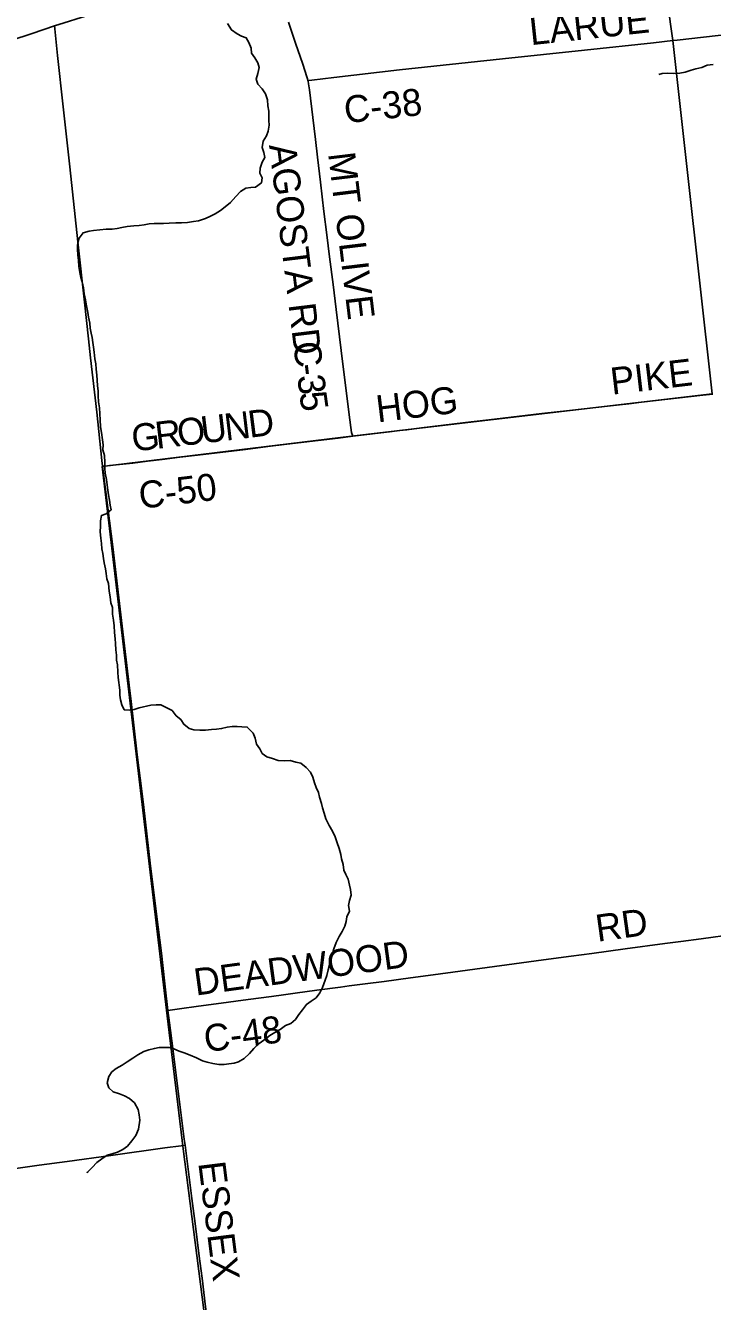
# Model space of a CAD drawing. Extents: x 1584893 to 1934202, y 663575 to 1091909.
# Drawn here: x 1740518 to 1748155, y 919866 to 934048 of the extents above; entities that cross this region are included whole.
import ezdxf

# ---------------------------------------------------------------- set-up
doc = ezdxf.new("R2010")
doc.units = 0
for name, color, linetype in [('GM_X_County_Road', 7, 'Continuous'), ('GM_X_County_Road_Text', 7, 'Continuous'), ('GM_X_Minor_River', 7, 'Continuous'), ('GM_X_Township', 7, 'Continuous')]:
    doc.layers.add(name, color=color, linetype=linetype)

msp = doc.modelspace()

# ---------------------------------------------------------------- linework, layer by layer
at = {"layer": 'GM_X_County_Road'}
for points in [[(1740840, 934043), (1740948, 934078), (1741137, 934136), (1741575, 934272), (1741827, 934348), (1741874, 934364), (1741920, 934379)], [(1747714, 933881), (1747761, 933886), (1748511, 933970), (1749147, 934042), (1749701, 934105), (1750239, 934164), (1750663, 934213), (1751430, 934296), (1751903, 934349), (1752896, 934460), (1752991, 934469), (1753049, 934473), (1753084, 934472), (1753123, 934468), (1753154, 934460), (1753192, 934449), (1753269, 934419), (1753584, 934278), (1753840, 934168), (1754320, 933956), (1754513, 933871)], [(1743657, 933436), (1743653, 933455), (1743646, 933478), (1743600, 933618), (1743521, 933851), (1743442, 934084)], [(1737758, 932862), (1737763, 932863), (1737769, 932865), (1737773, 932868), (1737788, 932878), (1737814, 932899), (1737880, 932947), (1737948, 932993), (1738004, 933027), (1738161, 933115), (1738262, 933170), (1738320, 933199), (1738380, 933225), (1738441, 933248), (1738596, 933301), (1738705, 933338), (1738814, 933373), (1739017, 933439), (1739204, 933501), (1739453, 933584), (1739842, 933713), (1740123, 933806), (1740590, 933960), (1740840, 934043)], [(1741375, 929149), (1741368, 929213), (1741310, 929752), (1741242, 930355), (1741219, 930567), (1741174, 930975), (1741099, 931644), (1741010, 932476), (1740937, 933145), (1740874, 933716), (1740844, 934010), (1740840, 934043)], [(1743657, 933436), (1743699, 933441), (1743944, 933471), (1744677, 933554), (1745819, 933678), (1746733, 933773), (1747500, 933857), (1747714, 933881)], [(1744155, 929482), (1744141, 929524), (1744115, 929720), (1744089, 929931), (1744070, 930078), (1744026, 930436), (1743970, 930892), (1743937, 931169), (1743897, 931478), (1743867, 931722), (1743836, 931982), (1743797, 932308), (1743763, 932585), (1743740, 932780), (1743711, 933025), (1743674, 933334), (1743665, 933399), (1743659, 933431), (1743657, 933436)], [(1744155, 929482), (1744594, 929537), (1744676, 929546), (1744757, 929555), (1744920, 929576), (1745409, 929635), (1745731, 929673), (1746256, 929735), (1746565, 929770), (1746826, 929799), (1747087, 929829), (1747226, 929845), (1747364, 929861), (1747788, 929909), (1748048, 929940), (1748158, 929952)], [(1741375, 929149), (1741402, 929151), (1741451, 929156), (1741712, 929184), (1741875, 929206), (1742038, 929224), (1742233, 929249), (1742429, 929272), (1742934, 929333), (1743243, 929373), (1743487, 929402), (1743992, 929462), (1744155, 929482)], [(1742101, 923100), (1742066, 923396), (1742028, 923738), (1741991, 924027), (1741905, 924738), (1741833, 925356), (1741812, 925537), (1741760, 925943), (1741687, 926568), (1741670, 926716), (1741592, 927372), (1741488, 928252), (1741434, 928686), (1741388, 929034), (1741375, 929149)], [(1742101, 923100), (1742150, 923108), (1742231, 923120), (1742442, 923149), (1742637, 923174), (1742994, 923223), (1743254, 923257), (1743384, 923275), (1743514, 923293), (1743758, 923325), (1744018, 923361), (1744115, 923374), (1744294, 923397), (1744505, 923424), (1744798, 923462), (1744993, 923489), (1745269, 923526), (1745512, 923559), (1745870, 923606), (1746113, 923640), (1746276, 923662), (1746584, 923703), (1746812, 923733), (1747186, 923784), (1747624, 923843), (1747803, 923866), (1748030, 923897), (1748404, 923947)], [(1742292, 921603), (1742283, 921670), (1742245, 921968), (1742181, 922469), (1742155, 922679), (1742118, 922964), (1742101, 923100)], [(1740410, 921342), (1740670, 921379), (1740979, 921422), (1741467, 921489), (1742068, 921572), (1742247, 921597), (1742292, 921603)], [(1742935, 916518), (1742930, 916557), (1742859, 917127), (1742812, 917485), (1742736, 918096), (1742717, 918251), (1742672, 918615), (1742623, 919006), (1742595, 919238), (1742569, 919432), (1742547, 919591), (1742519, 919807), (1742481, 920123), (1742449, 920369), (1742403, 920731), (1742368, 921009), (1742329, 921306), (1742292, 921603)]]:
    msp.add_lwpolyline(points, dxfattribs=at)
at = {"layer": 'GM_X_Minor_River'}
for points in [[(1742764, 934069), (1742807, 934000), (1742869, 933955), (1742920, 933930), (1742972, 933911), (1743001, 933860), (1743028, 933796), (1743029, 933740), (1743067, 933689), (1743100, 933632), (1743115, 933580), (1743102, 933514), (1743081, 933452), (1743100, 933398), (1743149, 933345), (1743184, 933290), (1743207, 933223), (1743212, 933157), (1743221, 933097), (1743224, 933043), (1743223, 932993), (1743225, 932940), (1743215, 932874), (1743195, 932823), (1743158, 932761), (1743150, 932693), (1743169, 932637), (1743179, 932582), (1743148, 932529), (1743125, 932461), (1743124, 932407), (1743149, 932354), (1743140, 932300), (1743075, 932251), (1743021, 932246), (1742967, 932239), (1742908, 932204), (1742855, 932149), (1742798, 932081), (1742739, 932032), (1742684, 931991), (1742626, 931956), (1742575, 931929), (1742519, 931903), (1742442, 931879), (1742386, 931870), (1742318, 931859), (1742250, 931856), (1742188, 931855), (1742115, 931852), (1742053, 931847), (1741949, 931849), (1741893, 931844), (1741835, 931832), (1741783, 931827), (1741722, 931820), (1741646, 931814), (1741588, 931802), (1741538, 931793), (1741480, 931786), (1741415, 931783), (1741343, 931778), (1741275, 931769), (1741225, 931764), (1741157, 931743), (1741116, 931686), (1741096, 931612), (1741097, 931562), (1741098, 931500), (1741107, 931437)], [(1748161, 933615), (1748095, 933606), (1748037, 933583), (1747970, 933568), (1747918, 933551), (1747850, 933530), (1747793, 933519), (1747717, 933514), (1747657, 933517), (1747595, 933514), (1747559, 933505)], [(1741107, 931437), (1741112, 931371), (1741123, 931303), (1741132, 931249), (1741146, 931198), (1741161, 931132), (1741169, 931067), (1741184, 930999), (1741197, 930931), (1741210, 930860), (1741219, 930806), (1741232, 930738), (1741237, 930685), (1741248, 930629), (1741258, 930579), (1741265, 930525), (1741272, 930474), (1741281, 930416), (1741290, 930344), (1741299, 930287), (1741302, 930229), (1741309, 930161), (1741316, 930107), (1741317, 930045), (1741324, 929986), (1741327, 929932), (1741328, 929866), (1741341, 929798), (1741349, 929667), (1741353, 929587), (1741362, 929523), (1741373, 929444), (1741380, 929386), (1741379, 929332), (1741394, 929269), (1741399, 929191), (1741400, 929123), (1741405, 929073), (1741418, 929002), (1741425, 928942), (1741432, 928884), (1741439, 928832), (1741452, 928771), (1741457, 928717), (1741469, 928665), (1741416, 928622), (1741361, 928602), (1741352, 928544), (1741353, 928484), (1741348, 928420), (1741355, 928350), (1741364, 928292), (1741367, 928233), (1741376, 928179), (1741384, 928125), (1741393, 928075), (1741406, 928008), (1741413, 927956), (1741420, 927898), (1741439, 927847), (1741448, 927761), (1741457, 927697), (1741468, 927630), (1741483, 927580), (1741486, 927506), (1741496, 927437), (1741505, 927375), (1741506, 927301), (1741515, 927231), (1741518, 927180), (1741523, 927110), (1741528, 927050), (1741531, 926994), (1741540, 926942), (1741543, 926861), (1741548, 926801), (1741566, 926661), (1741567, 926606), (1741574, 926554), (1741589, 926498), (1741616, 926443), (1741672, 926438), (1741724, 926445), (1741781, 926465), (1741911, 926492), (1741970, 926498), (1742022, 926499), (1742083, 926468), (1742147, 926435), (1742192, 926376), (1742245, 926333), (1742278, 926282), (1742338, 926235), (1742389, 926220), (1742455, 926215), (1742520, 926216), (1742584, 926225), (1742640, 926228), (1742698, 926233), (1742760, 926250), (1742815, 926255)], [(1742815, 926255), (1742869, 926258), (1742923, 926253), (1742983, 926250), (1743050, 926183), (1743069, 926127), (1743086, 926060), (1743123, 926008), (1743148, 925957), (1743199, 925918), (1743265, 925901), (1743327, 925880), (1743395, 925875), (1743461, 925878), (1743523, 925859), (1743577, 925850), (1743636, 925801), (1743687, 925748), (1743712, 925693), (1743731, 925631), (1743749, 925580), (1743774, 925524), (1743787, 925470), (1743808, 925401), (1743821, 925351), (1743838, 925292), (1743857, 925230), (1743894, 925155), (1743929, 925092), (1743960, 925030), (1743983, 924965), (1744006, 924899), (1744023, 924834), (1744032, 924784), (1744049, 924722), (1744056, 924661), (1744079, 924611), (1744106, 924560), (1744119, 924494), (1744132, 924444), (1744139, 924383), (1744120, 924324), (1744107, 924266), (1744118, 924203), (1744091, 924142), (1744082, 924088), (1744066, 924036), (1744037, 923978), (1744004, 923923), (1743972, 923855), (1743947, 923787), (1743926, 923715), (1743898, 923606), (1743883, 923552), (1743866, 923490), (1743849, 923438), (1743818, 923354), (1743789, 923297), (1743748, 923241), (1743693, 923204), (1743641, 923167), (1743596, 923107), (1743555, 923056), (1743520, 923000), (1743467, 922957), (1743407, 922932), (1743350, 922889), (1743291, 922856), (1743233, 922823), (1743168, 922772), (1743117, 922734), (1743056, 922679), (1743007, 922622), (1742948, 922565), (1742887, 922528), (1742837, 922516), (1742777, 922507), (1742725, 922500), (1742667, 922499), (1742601, 922510), (1742537, 922525), (1742485, 922542), (1742418, 922575), (1742350, 922603), (1742280, 922630), (1742227, 922649), (1742167, 922674), (1742115, 922687), (1742063, 922689), (1742003, 922688), (1741951, 922679), (1741890, 922662), (1741834, 922645), (1741767, 922606), (1741709, 922571), (1741646, 922530), (1741591, 922493), (1741526, 922454), (1741476, 922418), (1741443, 922367), (1741426, 922295)], [(1741426, 922295), (1741443, 922240), (1741494, 922196), (1741562, 922174), (1741620, 922151), (1741675, 922122), (1741728, 922075), (1741769, 921999), (1741782, 921940), (1741787, 921880), (1741772, 921782), (1741746, 921712), (1741699, 921653), (1741650, 921592), (1741598, 921554), (1741541, 921527), (1741481, 921506), (1741426, 921491), (1741368, 921452), (1741309, 921411), (1741260, 921355), (1741203, 921300), (1741215, 921306)]]:
    msp.add_lwpolyline(points, dxfattribs=at)
at = {"layer": 'GM_X_Township'}
for points in [[(1747311, 936737), (1747714, 933880), (1747874, 932446), (1748152, 929954), (1744140, 929482), (1741371, 929146), (1742091, 923042), (1742272, 921561), (1742922, 916471), (1743227, 913952), (1739940, 913938)], [(1760358, 914021), (1759934, 914025), (1758493, 914019), (1753982, 914000), (1748682, 913976), (1743227, 913952), (1742922, 916471), (1742272, 921561), (1742091, 923042), (1741371, 929146), (1744140, 929482), (1748152, 929954), (1747874, 932446), (1747714, 933880), (1747311, 936737)]]:
    msp.add_lwpolyline(points, dxfattribs=at)

# ---------------------------------------------------------------- texts
at = {"layer": 'GM_X_County_Road_Text'}
for s, rotation, p in [('LARUE', 6.1812, (1746136, 933829)), ('C-38', 6.1891, (1744075, 932961)), ('AGOSTA RD', 276.9763, (1743224, 932718)), ('MT OLIVE', 276.8937, (1743881, 932625)), ('C', 276.9367, (1743493, 930521)), ('-', 276.9737, (1743523, 930276)), ('PIKE', 6.7106, (1747038, 929944)), ('3', 277.0869, (1743538, 930153)), ('5', 277.812, (1743561, 929965)), ('HOG', 6.9683, (1744433, 929636)), ('O', 6.7767, (1742221, 929371)), ('U', 6.778, (1742483, 929402)), ('N', 6.7817, (1742745, 929433)), ('D', 7.2509, (1743010, 929465)), ('G', 6.7767, (1741714, 929311)), ('R', 6.7779, (1741976, 929342)), ('C-50', 6.8306, (1741795, 928675)), ('RD', 7.9189, (1746877, 923863)), ('DEADWOOD', 7.7236, (1742411, 923265)), ('C-48', 7.5505, (1742521, 922635)), ('ESSEX', 277.1524, (1742438, 921406))]:
    msp.add_text(s, height=300, rotation=rotation, dxfattribs=at).set_placement(p)

doc.saveas('drawing.dxf')
